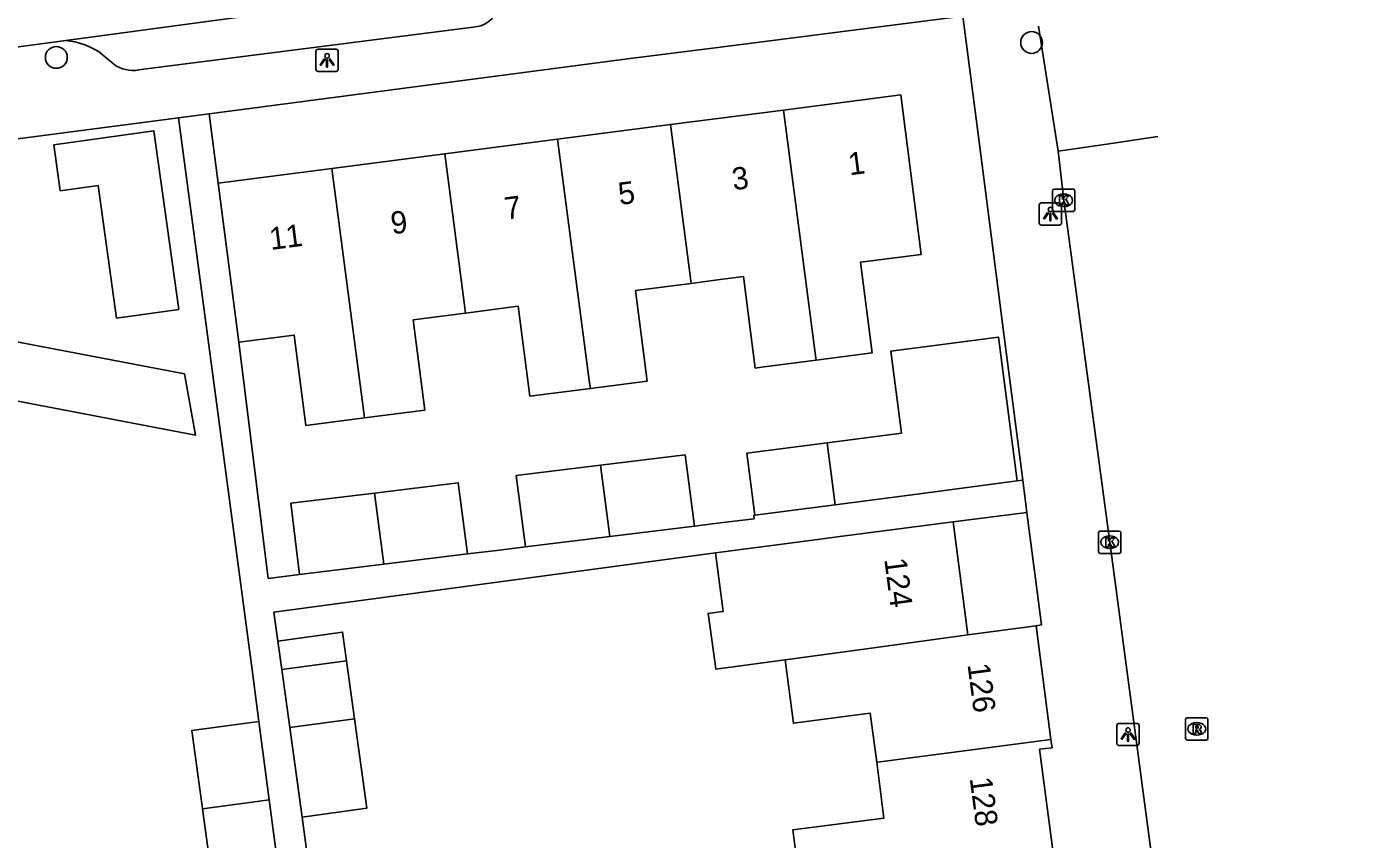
# Model space of a CAD drawing. Extents: x 163150 to 163546, y 380933 to 381635.
# Drawn here: x 163469.1 to 163528.8, y 381055.2 to 381091.7 of the extents above; entities that cross this region are included whole.
import ezdxf

# ---------------------------------------------------------------- set-up
doc = ezdxf.new("R2010")
doc.units = 0
for name, color, linetype in [('IMGEO_Boom', 7, 'Continuous'), ('IMGEO_Kolk', 7, 'Continuous'), ('IMGEO_Lichtpunt', 7, 'Continuous'), ('IMGEO_Muur', 7, 'Continuous'), ('IMGEO_Pand', 7, 'Continuous'), ('IMGEO_Pand_nummerreeks', 7, 'Continuous'), ('IMGEO_Rijbaan_lokaal_open', 7, 'Continuous'), ('IMGEO_Rioolput', 7, 'Continuous'), ('IMGEO_Voetpad_open', 7, 'Continuous')]:
    doc.layers.add(name, color=color, linetype=linetype)

msp = doc.modelspace()

# ---------------------------------------------------------------- linework, layer by layer
at = {"layer": 'IMGEO_Boom'}
for centre in [(163514.189, 381090.952), (163470.461, 381090.286)]:
    msp.add_circle(centre, 0.489, dxfattribs=at)
at = {"layer": 'IMGEO_Kolk'}
for p, q in [((163515.126, 381083.456), (163515.126, 381084.308)), ((163515.201, 381084.382), (163516.053, 381084.382)), ((163515.614, 381084.162), (163515.639, 381084.162)), ((163516.127, 381084.308), (163516.127, 381083.456)), ((163515.637, 381083.602), (163515.612, 381083.602)), ((163516.053, 381083.382), (163515.201, 381083.382)), ((163517.19, 381068.13), (163517.19, 381068.982)), ((163517.265, 381069.056), (163518.117, 381069.056)), ((163517.678, 381068.836), (163517.703, 381068.836)), ((163518.191, 381068.982), (163518.191, 381068.13)), ((163518.117, 381068.056), (163517.265, 381068.056)), ((163517.701, 381068.276), (163517.676, 381068.276))]:
    msp.add_line(p, q, dxfattribs=at)
for points in [[(163515.126, 381083.456), (163515.126, 381084.308)], [(163515.201, 381084.382), (163516.053, 381084.382)], [(163516.127, 381084.308), (163516.127, 381083.456)], [(163515.447, 381084.082), (163515.57, 381084.082), (163515.57, 381083.931), (163515.7, 381084.082), (163515.864, 381084.082), (163515.718, 381083.931), (163515.871, 381083.682), (163515.719, 381083.682), (163515.634, 381083.846), (163515.57, 381083.779), (163515.57, 381083.682), (163515.447, 381083.682), (163515.447, 381084.082)], [(163516.053, 381083.382), (163515.201, 381083.382)], [(163517.19, 381068.13), (163517.19, 381068.982)], [(163517.265, 381069.056), (163518.117, 381069.056)], [(163517.511, 381068.756), (163517.634, 381068.756), (163517.634, 381068.605), (163517.764, 381068.756), (163517.928, 381068.756), (163517.782, 381068.605), (163517.935, 381068.356), (163517.783, 381068.356), (163517.698, 381068.52), (163517.634, 381068.453), (163517.634, 381068.356), (163517.511, 381068.356), (163517.511, 381068.756)], [(163518.191, 381068.982), (163518.191, 381068.13)], [(163518.117, 381068.056), (163517.265, 381068.056)]]:
    msp.add_lwpolyline(points, dxfattribs=at)
for centre, start, end in [((163515.203, 381084.306), 91.55205, 178.44795), ((163515.203, 381084.306), 91.55205, 178.44795), ((163516.051, 381084.306), 1.55205, 88.44795), ((163516.051, 381084.306), 1.55205, 88.44795), ((163515.203, 381083.458), 181.55205, 268.44795), ((163515.203, 381083.458), 181.55205, 268.44795), ((163516.051, 381083.458), 271.55205, 358.44795), ((163516.051, 381083.458), 271.55205, 358.44795), ((163517.267, 381068.98), 91.55205, 178.44795), ((163517.267, 381068.98), 91.55205, 178.44795), ((163518.115, 381068.98), 1.55205, 88.44795), ((163518.115, 381068.98), 1.55205, 88.44795), ((163517.267, 381068.132), 181.55205, 268.44795), ((163517.267, 381068.132), 181.55205, 268.44795), ((163518.115, 381068.132), 271.55205, 358.44795), ((163518.115, 381068.132), 271.55205, 358.44795)]:
    msp.add_arc(centre, 0.0765, start, end, dxfattribs=at)
for centre, major_axis, ratio, start_param, end_param in [((163515.613, 381083.882), (-0.387, 0.002), 0.722429, 4.712389, 7.853982), ((163515.638, 381083.882), (-0.39, 0.002), 0.717154, 1.570796, 4.712389), ((163517.677, 381068.556), (-0.387, 0.002), 0.722429, 4.712389, 7.853982), ((163517.702, 381068.556), (-0.39, 0.002), 0.717154, 1.570796, 4.712389)]:
    msp.add_ellipse(centre, major_axis=major_axis, ratio=ratio, start_param=start_param, end_param=end_param, dxfattribs=at)
at = {"layer": 'IMGEO_Lichtpunt'}
for p, q in [((163482.103, 381090.56), (163482.103, 381089.753)), ((163482.103, 381090.56), (163482.103, 381089.753)), ((163483.005, 381090.655), (163482.197, 381090.655)), ((163483.005, 381090.655), (163482.197, 381090.655)), ((163483.099, 381089.753), (163483.099, 381090.56)), ((163483.099, 381089.753), (163483.099, 381090.56)), ((163482.197, 381089.659), (163483.005, 381089.659)), ((163482.197, 381089.659), (163483.005, 381089.659)), ((163514.536, 381083.67), (163514.536, 381082.863)), ((163514.536, 381083.67), (163514.536, 381082.863)), ((163515.438, 381083.765), (163514.63, 381083.765)), ((163515.438, 381083.765), (163514.63, 381083.765)), ((163515.532, 381082.863), (163515.532, 381083.67)), ((163515.532, 381082.863), (163515.532, 381083.67)), ((163514.63, 381082.769), (163515.438, 381082.769)), ((163514.63, 381082.769), (163515.438, 381082.769)), ((163518.015, 381060.343), (163518.015, 381059.536)), ((163518.015, 381060.343), (163518.015, 381059.536)), ((163518.917, 381060.438), (163518.109, 381060.438)), ((163518.917, 381060.438), (163518.109, 381060.438)), ((163519.011, 381059.536), (163519.011, 381060.343)), ((163519.011, 381059.536), (163519.011, 381060.343)), ((163518.109, 381059.442), (163518.917, 381059.442)), ((163518.109, 381059.442), (163518.917, 381059.442))]:
    msp.add_line(p, q, dxfattribs=at)
for points in [[(163482.477, 381090.224), (163482.516, 381090.196), (163482.328, 381089.934), (163482.29, 381089.961), (163482.477, 381090.224)], [(163482.579, 381090.176), (163482.626, 381090.176), (163482.626, 381089.854), (163482.579, 381089.854), (163482.579, 381090.176)], [(163482.689, 381090.196), (163482.727, 381090.223), (163482.914, 381089.961), (163482.875, 381089.933), (163482.689, 381090.196)], [(163514.91, 381083.334), (163514.949, 381083.306), (163514.761, 381083.044), (163514.723, 381083.071), (163514.91, 381083.334)], [(163515.012, 381083.286), (163515.059, 381083.286), (163515.059, 381082.964), (163515.012, 381082.964), (163515.012, 381083.286)], [(163515.122, 381083.306), (163515.16, 381083.333), (163515.347, 381083.071), (163515.308, 381083.043), (163515.122, 381083.306)], [(163518.389, 381060.007), (163518.428, 381059.979), (163518.24, 381059.717), (163518.202, 381059.744), (163518.389, 381060.007)], [(163518.491, 381059.959), (163518.538, 381059.959), (163518.538, 381059.637), (163518.491, 381059.637), (163518.491, 381059.959)], [(163518.601, 381059.979), (163518.639, 381060.006), (163518.826, 381059.744), (163518.787, 381059.716), (163518.601, 381059.979)]]:
    msp.add_lwpolyline(points, dxfattribs=at)
for centre in [(163482.602, 381090.358), (163515.035, 381083.468), (163518.514, 381060.141)]:
    msp.add_circle(centre, 0.0994, dxfattribs=at)
for centre, start, end in [((163482.197, 381090.56), 90, 180), ((163482.197, 381090.56), 90, 180), ((163483.005, 381090.56), 0, 90), ((163483.005, 381090.56), 0, 90), ((163482.197, 381089.753), 180, 270), ((163482.197, 381089.753), 180, 270), ((163483.005, 381089.753), 270, 0), ((163483.005, 381089.753), 270, 360), ((163514.63, 381083.67), 90, 180), ((163514.63, 381083.67), 90, 180), ((163515.438, 381083.67), 0, 90), ((163515.438, 381083.67), 0, 90), ((163514.63, 381082.863), 180, 270), ((163514.63, 381082.863), 180, 270), ((163515.438, 381082.863), 270, 0), ((163515.438, 381082.863), 270, 360), ((163518.109, 381060.343), 90, 180), ((163518.109, 381060.343), 90, 180), ((163518.917, 381060.343), 0, 90), ((163518.917, 381060.343), 0, 90), ((163518.109, 381059.536), 180, 270), ((163518.109, 381059.536), 180, 270), ((163518.917, 381059.536), 270, 0), ((163518.917, 381059.536), 270, 360)]:
    msp.add_arc(centre, 0.0946, start, end, dxfattribs=at)
at = {"layer": 'IMGEO_Muur'}
msp.add_lwpolyline([(163511.896, 381086.04), (163512.961, 381077.779)], dxfattribs=at)
at = {"layer": 'IMGEO_Pand'}
for points in [[(163503.06, 381087.926), (163508.321, 381088.604), (163509.243, 381081.457), (163506.516, 381081.105), (163507.04, 381077.04), (163504.533, 381076.716)], [(163497.998, 381087.273), (163500, 381087.531), (163503.06, 381087.926)], [(163503.06, 381087.926), (163504.492, 381077.026), (163504.533, 381076.716)], [(163492.937, 381086.62), (163497.998, 381087.273)], [(163498.932, 381080.159), (163498.901, 381080.398), (163497.998, 381087.273)], [(163473.163, 381078.599), (163472.335, 381084.549), (163470.636, 381084.312), (163470.35, 381086.368), (163474.838, 381086.992), (163475.953, 381078.988), (163473.163, 381078.599)], [(163487.875, 381085.967), (163492.937, 381086.62)], [(163494.405, 381075.446), (163494.372, 381075.695), (163492.937, 381086.62)], [(163482.813, 381085.314), (163487.875, 381085.967)], [(163488.814, 381078.828), (163488.782, 381079.068), (163487.875, 381085.967)], [(163477.721, 381084.657), (163482.813, 381085.314)], [(163482.813, 381085.314), (163484.253, 381074.366), (163484.284, 381074.127)], [(163478.642, 381077.52), (163478.361, 381079.699), (163477.721, 381084.657)], [(163498.932, 381080.159), (163496.435, 381079.837), (163496.959, 381075.776), (163494.405, 381075.446)], [(163504.533, 381076.716), (163502.082, 381076.4), (163501.8, 381076.364), (163501.271, 381080.461), (163500, 381080.297), (163498.932, 381080.159)], [(163488.814, 381078.828), (163486.466, 381078.525), (163486.989, 381074.476), (163484.284, 381074.127)], [(163494.405, 381075.446), (163491.694, 381075.096), (163491.173, 381079.132), (163488.814, 381078.828)], [(163465.15, 381078.205), (163476.21, 381076.097), (163476.703, 381073.36), (163464.664, 381075.652)], [(163484.284, 381074.127), (163481.653, 381073.787), (163481.13, 381077.841), (163478.642, 381077.52)], [(163505.019, 381073.013), (163508.356, 381073.449), (163507.877, 381077.116), (163512.706, 381077.746), (163513.547, 381071.301)], [(163501.777, 381069.765), (163501.415, 381072.543), (163505.019, 381073.013)], [(163505.019, 381073.013), (163505.384, 381070.236)], [(163494.857, 381072.006), (163498.651, 381072.472), (163499.07, 381069.28)], [(163491.493, 381068.349), (163491.073, 381071.541), (163494.857, 381072.006)], [(163495.276, 381068.814), (163494.857, 381072.006)], [(163484.727, 381070.762), (163488.481, 381071.223), (163488.9, 381068.031)], [(163513.547, 381071.301), (163508.718, 381070.671), (163505.384, 381070.236)], [(163481.369, 381067.106), (163480.977, 381070.302), (163484.727, 381070.762)], [(163485.147, 381067.57), (163484.727, 381070.762)], [(163505.384, 381070.236), (163501.777, 381069.765)], [(163495.276, 381068.814), (163499.07, 381069.28)], [(163500.014, 381068.079), (163503.572, 381068.542), (163505.714, 381068.821), (163510.672, 381069.468)], [(163511.333, 381064.399), (163510.672, 381069.468)], [(163491.493, 381068.349), (163495.276, 381068.814)], [(163485.147, 381067.57), (163488.9, 381068.031)], [(163500.014, 381068.079), (163500.356, 381065.451), (163500.004, 381065.405), (163499.686, 381065.363), (163500, 381063.104), (163500.034, 381062.86), (163503.143, 381063.284)], [(163481.369, 381067.106), (163485.147, 381067.57)], [(163483.475, 381063.234), (163483.297, 381064.527), (163480.394, 381064.127)], [(163503.143, 381063.284), (163506.459, 381063.735), (163507.214, 381063.838), (163511.333, 381064.399)], [(163514.394, 381064.816), (163511.333, 381064.399)], [(163514.394, 381064.816), (163515.059, 381059.721)], [(163480.394, 381064.127), (163480.569, 381062.854)], [(163480.569, 381062.854), (163483.475, 381063.234)], [(163483.831, 381060.646), (163483.475, 381063.234)], [(163503.143, 381063.284), (163503.514, 381060.443), (163506.831, 381060.876), (163506.957, 381060.892), (163507.243, 381058.7)], [(163480.569, 381062.854), (163480.927, 381060.247)], [(163477.017, 381056.601), (163476.995, 381056.76), (163476.986, 381056.826), (163476.539, 381060.118), (163479.544, 381060.526)], [(163480.01, 381057.007), (163479.544, 381060.526)], [(163483.831, 381060.646), (163480.927, 381060.247)], [(163480.927, 381060.247), (163481.48, 381056.231)], [(163481.48, 381056.231), (163484.383, 381056.63), (163483.831, 381060.646)], [(163507.243, 381058.7), (163507.394, 381058.72), (163515.059, 381059.721)], [(163515.059, 381059.721), (163515.108, 381059.347), (163514.551, 381059.274), (163515.156, 381054.634)], [(163507.243, 381058.7), (163507.57, 381056.192), (163503.481, 381055.659), (163503.808, 381053.153)], [(163477.017, 381056.601), (163479.566, 381056.947), (163480.01, 381057.007)], [(163480.591, 381052.617), (163480.01, 381057.007)], [(163480.591, 381052.617), (163477.611, 381052.228), (163477.017, 381056.601)]]:
    msp.add_lwpolyline(points, dxfattribs=at)
at = {"layer": 'IMGEO_Rijbaan_lokaal_open'}
for points in [[(163507.201, 381095.911), (163500, 381094.955), (163488.993, 381093.493), (163470.891, 381091.039)], [(163514.495, 381091.686), (163515.38, 381086.08)], [(163470.891, 381091.039), (163468.211, 381090.689)], [(163519.851, 381086.738), (163517.56, 381086.401), (163515.38, 381086.08)], [(163515.38, 381086.08), (163515.628, 381083.882), (163517.691, 381068.556), (163520.526, 381047.354), (163523.013, 381028.635), (163525.88, 381007.238), (163526.859, 381000), (163528.841, 380985.339)]]:
    msp.add_lwpolyline(points, dxfattribs=at)
at = {"layer": 'IMGEO_Rioolput'}
for p, q in [((163521.094, 381059.763), (163521.094, 381060.615)), ((163521.169, 381060.689), (163522.021, 381060.689)), ((163521.582, 381060.469), (163521.607, 381060.469)), ((163522.095, 381060.615), (163522.095, 381059.763)), ((163522.021, 381059.689), (163521.169, 381059.689)), ((163521.605, 381059.909), (163521.58, 381059.909))]:
    msp.add_line(p, q, dxfattribs=at)
for points in [[(163521.094, 381059.763), (163521.094, 381060.615)], [(163521.169, 381060.689), (163522.021, 381060.689)], [(163521.683, 381060.387), (163521.431, 381060.389), (163521.431, 381059.989)], [(163521.609, 381060.308), (163521.555, 381060.308), (163521.555, 381060.227)], [(163521.555, 381060.227), (163521.607, 381060.227)], [(163522.095, 381060.615), (163522.095, 381059.763)], [(163522.021, 381059.689), (163521.169, 381059.689)], [(163521.431, 381059.989), (163521.555, 381059.989), (163521.555, 381060.151), (163521.566, 381060.151)], [(163521.613, 381060.122), (163521.684, 381059.989), (163521.824, 381059.989), (163521.759, 381060.115)]]:
    msp.add_lwpolyline(points, dxfattribs=at)
for centre, radius, start, end in [((163521.171, 381060.613), 0.0765, 91.55205, 178.44795), ((163521.171, 381060.613), 0.0765, 91.55205, 178.44795), ((163521.591, 381060.416), 0.19, 274.7715, 282.96867), ((163521.615, 381060.212), 0.0964, 77.00612, 93.18647), ((163521.629, 381060.269), 0.0378, 276.66336, 79.67722), ((163521.682, 381060.277), 0.109, 350.36119, 89.41601), ((163521.68, 381060.277), 0.112, 277.58423, 350.98172), ((163522.019, 381060.613), 0.0765, 1.55205, 88.44795), ((163522.019, 381060.613), 0.0765, 1.55205, 88.44795), ((163521.171, 381059.765), 0.0765, 181.55205, 268.44795), ((163521.171, 381059.765), 0.0765, 181.55205, 268.44795), ((163521.565, 381060.098), 0.0533, 26.02933, 88.69889), ((163521.664, 381060.062), 0.108, 29.51342, 73.79051), ((163522.019, 381059.765), 0.0765, 271.55205, 358.44795), ((163522.019, 381059.765), 0.0765, 271.55205, 358.44795)]:
    msp.add_arc(centre, radius, start, end, dxfattribs=at)
for centre, major_axis, ratio, start_param, end_param in [((163521.581, 381060.189), (-0.387, 0.002), 0.722429, 4.712389, 7.853982), ((163521.606, 381060.189), (-0.39, 0.002), 0.717154, 1.570796, 4.712389)]:
    msp.add_ellipse(centre, major_axis=major_axis, ratio=ratio, start_param=start_param, end_param=end_param, dxfattribs=at)
at = {"layer": 'IMGEO_Voetpad_open'}
for points in [[(163511.11, 381092.135), (163500, 381090.719), (163496.185, 381090.233), (163477.314, 381087.764)], [(163511.11, 381092.135), (163511.896, 381086.04), (163512.961, 381077.779), (163513.791, 381071.345)], [(163489.154, 381091.648), (163474.153, 381089.724)], [(163473.04, 381089.982), (163472.425, 381090.499)], [(163477.314, 381087.764), (163475.944, 381087.585)], [(163477.314, 381087.764), (163477.721, 381084.657)], [(163475.944, 381087.585), (163462.994, 381085.891), (163449.567, 381084.29)], [(163479.544, 381060.526), (163479.238, 381062.834), (163475.944, 381087.585)], [(163478.642, 381077.52), (163479.96, 381066.933), (163481.369, 381067.106)], [(163513.547, 381071.301), (163513.791, 381071.345)], [(163513.791, 381071.345), (163513.978, 381069.894)], [(163510.672, 381069.468), (163513.978, 381069.894)], [(163513.978, 381069.894), (163514.629, 381064.847), (163514.394, 381064.816)], [(163499.07, 381069.28), (163500.341, 381069.436), (163501.748, 381069.609), (163501.73, 381069.759), (163501.777, 381069.765)], [(163480.394, 381064.127), (163480.217, 381065.416), (163482.882, 381065.783), (163500.014, 381068.079)], [(163488.9, 381068.031), (163490.212, 381068.192), (163491.493, 381068.349)], [(163481.834, 381053.659), (163481.48, 381056.231)]]:
    msp.add_lwpolyline(points, dxfattribs=at)
for centre, radius, start, end in [((163489.116, 381092.855), 1.208, 271.81584, 337.55235), ((163470.607, 381087.784), 3.268, 56.1981, 85.01564), ((163473.901, 381091.166), 1.464, 233.97943, 279.91857)]:
    msp.add_arc(centre, radius, start, end, dxfattribs=at)

# ---------------------------------------------------------------- texts
at = {"layer": 'IMGEO_Pand_nummerreeks'}
for s, rotation, p in [('1', 7.34983, (163506.031, 381085.001)), ('3', 7.34983, (163500.818, 381084.328)), ('5', 7.34983, (163495.718, 381083.67)), ('7', 7.34983, (163490.618, 381083.012)), ('9', 7.34983, (163485.518, 381082.355)), ('11', 7.34983, (163480.075, 381081.654)), ('124', 277.41959, (163507.582, 381067.796)), ('126', 277.43678, (163511.313, 381063.08)), ('128', 277.43105, (163511.412, 381057.979))]:
    msp.add_text(s, height=1, rotation=rotation, dxfattribs=at).set_placement(p)

doc.saveas('drawing.dxf')
